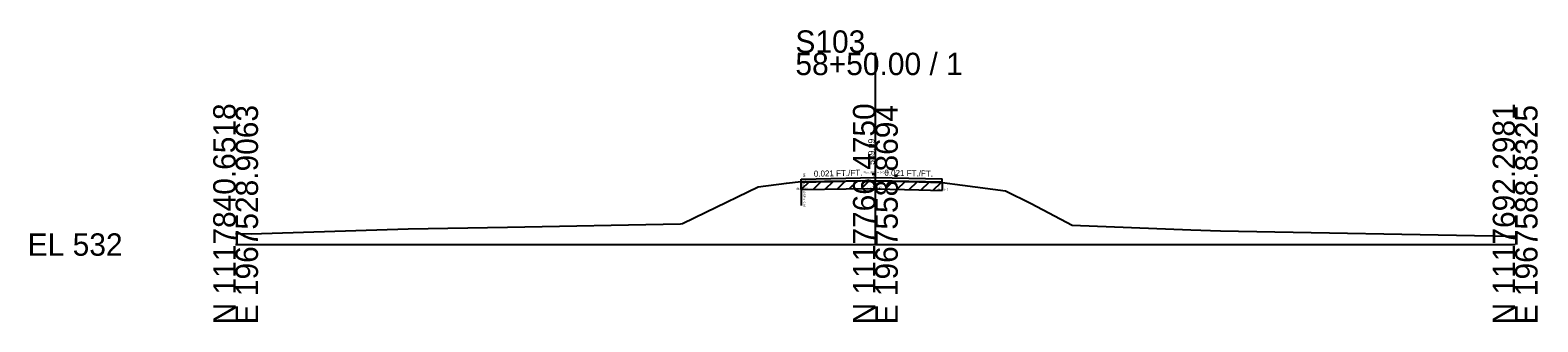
# Model space of a CAD drawing. Extents: x -26 to 163, y -10 to 24018.
# Drawn here: x -25.7 to 162.8, y 7990.3 to 8026.9 of the extents above; entities that cross this region are included whole.
import ezdxf

# ---------------------------------------------------------------- set-up
doc = ezdxf.new("R2010")
doc.units = 0
for name, color, linetype in [('RD_GPK_XS_Cell', 7, 'Continuous'), ('RD_XS_ExGround', 7, 'Continuous'), ('RD_XS_ExPaveRet', 7, 'Continuous'), ('RD_XS_Misc_Line', 7, 'Continuous'), ('RD_XS_PaveOvlay_CP', 7, 'Continuous'), ('RD_XS_TX_Elev_EX', 7, 'Continuous'), ('RD_XS_TX_ExEOP', 7, 'Continuous'), ('RD_XS_TX_Notes', 7, 'Continuous'), ('RD_XS_TX_Profile', 7, 'Continuous'), ('RD_XS_TX_Slope', 7, 'Continuous')]:
    doc.layers.add(name, color=color, linetype=linetype)

msp = doc.modelspace()

# ---------------------------------------------------------------- linework, layer by layer
at = {"layer": 'RD_GPK_XS_Cell'}
for p, q in [((80, 8000), (80, 8024.03)), ((0, 8000), (80, 8000)), ((80, 8000), (160, 8000))]:
    msp.add_line(p, q, dxfattribs=at)
at = {"layer": 'RD_XS_ExGround'}
msp.add_lwpolyline([(0, 8001.38), (1.96, 8001.36), (21.57, 8001.96), (33.99, 8002.19), (55.63, 8002.59), (55.89, 8002.62), (58.79, 8004.05), (65.35, 8007.22), (68.88, 8007.67), (70.73, 8007.89), (73.65, 8007.93), (79.07, 8008.01), (80, 8007.99), (85.45, 8007.85), (88.34, 8007.77), (90.91, 8007.44), (96.29, 8006.72), (99.47, 8005.15), (104.62, 8002.41), (119.45, 8001.84), (123.14, 8001.7), (159.48, 8001.05), (160, 8001.04)], dxfattribs=at)
at = {"layer": 'RD_XS_ExPaveRet'}
for p, q in [((70.73, 8006.89), (71.75, 8007.91)), ((70.73, 8006.89), (70.73, 8007.89)), ((72.23, 8006.91), (73.25, 8007.93)), ((73.65, 8006.93), (79.07, 8007.01)), ((73.73, 8006.93), (74.75, 8007.95)), ((75.23, 8006.95), (76.25, 8007.97)), ((76.73, 8006.98), (77.75, 8007.99)), ((78.23, 8007), (79.24, 8008)), ((79.07, 8007.01), (80, 8006.99)), ((79.73, 8006.99), (80.71, 8007.97)), ((80, 8006.99), (85.45, 8006.85)), ((81.23, 8006.95), (82.21, 8007.93)), ((82.74, 8006.92), (83.71, 8007.89)), ((84.24, 8006.88), (85.21, 8007.85)), ((85.74, 8006.84), (86.71, 8007.82)), ((87.24, 8006.8), (88.21, 8007.78)), ((88.34, 8007.77), (88.34, 8006.77)), ((70.73, 8006.89), (73.65, 8006.93)), ((85.45, 8006.85), (88.34, 8006.77))]:
    msp.add_line(p, q, dxfattribs=at)
at = {"layer": 'RD_XS_Misc_Line'}
msp.add_line((70.73, 8007.89), (70.73, 8004.89), dxfattribs=at)
at = {"layer": 'RD_XS_PaveOvlay_CP'}
for p, q in [((70.73, 8008.21), (80, 8008.41)), ((70.73, 8007.89), (70.73, 8008.21)), ((80, 8007.99), (70.73, 8007.79)), ((80, 8008.41), (88.34, 8008.23)), ((88.34, 8007.81), (80, 8007.99)), ((88.34, 8007.77), (88.34, 8008.23))]:
    msp.add_line(p, q, dxfattribs=at)

# ---------------------------------------------------------------- texts
at = {"layer": 'RD_GPK_XS_Cell'}
for s, p in [('S103', (70, 8024.03)), ('58+50.00 / 1', (70, 8021.23)), ('EL 532', (-26, 7998.6))]:
    msp.add_text(s, height=2.8, dxfattribs=at).set_placement(p)
for s, p in [('N 1117840.6518', (0, 7990)), ('E 1967528.9063', (2.8, 7990)), ('N 1117766.4750', (80, 7990)), ('E 1967558.8694', (82.8, 7990)), ('N 1117692.2981', (160, 7990)), ('E 1967588.8325', (162.8, 7990))]:
    msp.add_text(s, height=2.8, rotation=90, dxfattribs=at).set_placement(p)
at = {"layer": 'RD_XS_TX_Elev_EX'}
msp.add_text('539.99', height=0.8, rotation=90, dxfattribs=at).set_placement((79.9, 8009.99))
at = {"layer": 'RD_XS_TX_ExEOP'}
for s, p in [('EOP-L', (70.68, 8008.21)), ('EOP-R', (88.29, 8008.23))]:
    msp.add_text(s, height=0.1, rotation=270, dxfattribs=at).set_placement(p)
at = {"layer": 'RD_XS_TX_Notes'}
msp.add_text(' Min. Distance @CP = -0.10', height=0.25, rotation=270, dxfattribs=at).set_placement((70.98, 8008.99))
for s, p in [('Elev. @CL = 540.41', (78.49, 8008.91)), (' dE= 0.32', (70.02, 8006.89)), (' dE= 0.42', (79.29, 8006.99)), (' dE= 0.46', (87.63, 8006.77))]:
    msp.add_text(s, height=0.25, dxfattribs=at).set_placement(p)
at = {"layer": 'RD_XS_TX_Profile'}
msp.add_text('CL', height=0.25, dxfattribs=at).set_placement((79.77, 8008.41))
at = {"layer": 'RD_XS_TX_Slope'}
for rotation, p in [(1.1916, (72.31, 8008.5)), (358.8084, (81.12, 8008.63))]:
    msp.add_text('0.021 FT./FT.', height=0.75, rotation=rotation, dxfattribs=at).set_placement(p)

doc.saveas('drawing.dxf')
